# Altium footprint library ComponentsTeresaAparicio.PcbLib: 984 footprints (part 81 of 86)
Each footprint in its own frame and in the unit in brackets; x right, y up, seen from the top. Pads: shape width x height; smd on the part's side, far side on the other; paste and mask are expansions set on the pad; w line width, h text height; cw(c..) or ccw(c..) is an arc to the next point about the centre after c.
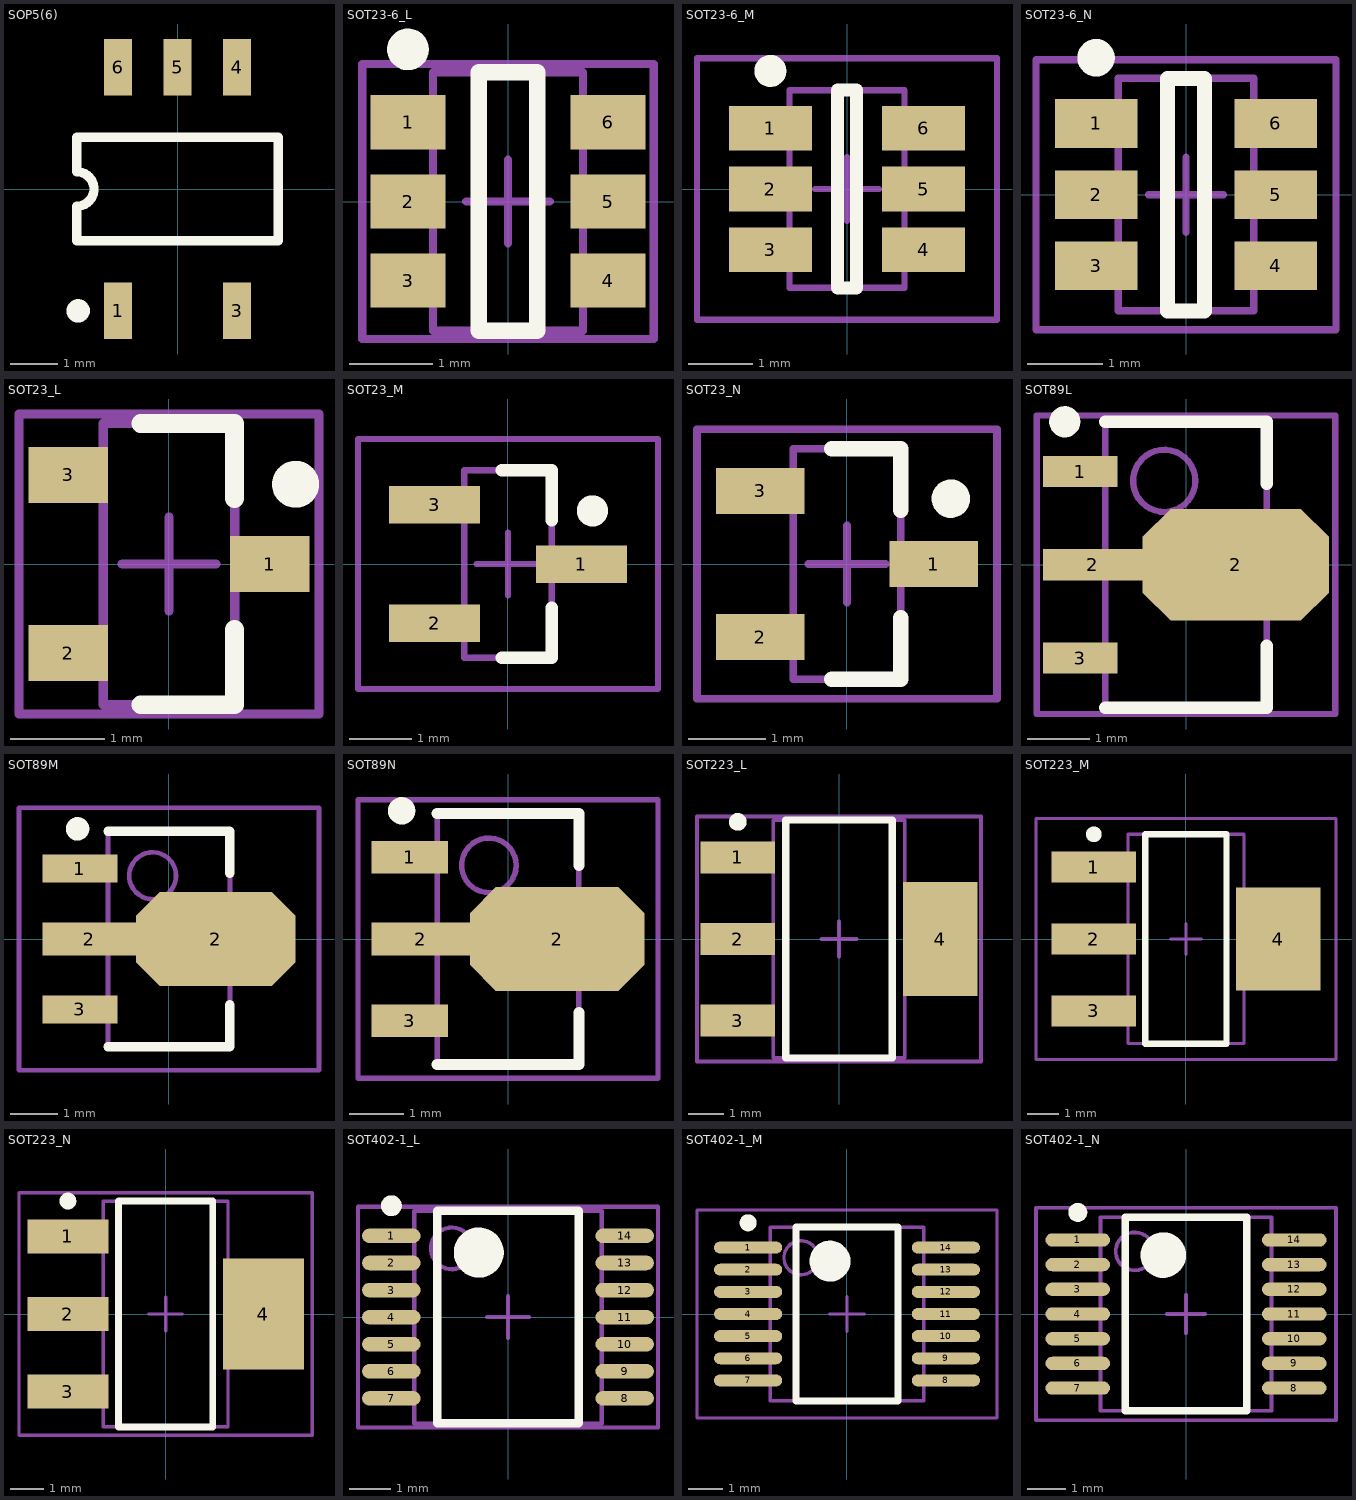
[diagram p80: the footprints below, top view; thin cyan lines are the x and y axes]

## SOP5(6) [mm] "Small Outline; 6 Leads (1 Absent); Body Width 4.4 mm; Pitch 1.27 mm"
height 2.4
pads (5):
  rect 0.6x1.2 smd: 1(-1.27,-2.6) 3(1.27,-2.6) 4(1.27,2.6) 5(0,2.6) 6(-1.27,2.6)
Top Overlay:
  circle w0.25: c-2.12,-2.6 r0.125
  lines w0.2: -2.15,-1.1 2.15,-1.1 2.15,1.1 -2.15,1.1 -2.15,0.367 cw(c-2.15,0) -2.15,-0.367 -2.15,-1.1

## SOT23-6_L [mm] "SOT23, 6-Leads, Body 2.9x1.6mm, Pitch 0.95mm, Lead Span 2.7mm, IPC High Density"
height 1.45
pads (6):
  rect 0.9x0.65 smd: 1(-1.2,0.95) 2(-1.2,0) 3(-1.2,-0.95) 4(1.2,-0.95) 5(1.2,0) 6(1.2,0.95)
Top Overlay:
  circle w0.25: c-1.2,1.825 r0.125
  lines w0.2: -0.35,-1.55 0.35,-1.55 0.35,1.55 -0.35,1.55 -0.35,-1.55
Mechanical 13:
  lines w0.1: -0.9,-1.55 -0.9,1.55 0.9,1.55 0.9,-1.55 -0.9,-1.55
Mechanical 15:
  lines w0.1: -0.5,0 0.5,0 ; 0,-0.5 0,0.5 ; -1.75,-1.65 -1.75,1.65 1.75,1.65 1.75,-1.65 -1.75,-1.65
3D body: height 1.45, standoff 0, extent -0.9,-1.55 0.9,1.55

## SOT23-6_M [mm] "SOT23, 6-Leads, Body 2.9x1.6mm, Pitch 0.95mm, Lead Span 2.7mm, IPC Low Density"
height 1.45
pads (6):
  rect 1.3x0.7 smd: 1(-1.2,0.95) 2(-1.2,0) 3(-1.2,-0.95) 4(1.2,-0.95) 5(1.2,0) 6(1.2,0.95)
Top Overlay:
  circle w0.25: c-1.2,1.85 r0.125
  lines w0.2: -0.15,-1.55 0.15,-1.55 0.15,1.55 -0.15,1.55 -0.15,-1.55
Mechanical 13:
  lines w0.1: -0.9,-1.55 -0.9,1.55 0.9,1.55 0.9,-1.55 -0.9,-1.55
Mechanical 15:
  lines w0.1: -0.5,0 0.5,0 ; 0,-0.5 0,0.5 ; -2.35,-2.05 -2.35,2.05 2.35,2.05 2.35,-2.05 -2.35,-2.05
3D body: height 1.45, standoff 0, extent -0.9,-1.55 0.9,1.55

## SOT23-6_N [mm] "SOT23, 6-Leads, Body 2.9x1.6mm, Pitch 0.95mm, Lead Span 2.7mm, IPC Medium Density"
height 1.45
pads (6):
  rect 1.1x0.65 smd: 1(-1.2,0.95) 2(-1.2,0) 3(-1.2,-0.95) 4(1.2,-0.95) 5(1.2,0) 6(1.2,0.95)
Top Overlay:
  circle w0.25: c-1.2,1.825 r0.125
  lines w0.2: -0.25,-1.55 0.25,-1.55 0.25,1.55 -0.25,1.55 -0.25,-1.55
Mechanical 13:
  lines w0.1: -0.9,-1.55 -0.9,1.55 0.9,1.55 0.9,-1.55 -0.9,-1.55
Mechanical 15:
  lines w0.1: -0.5,0 0.5,0 ; 0,-0.5 0,0.5 ; -2,-1.8 -2,1.8 2,1.8 2,-1.8 -2,-1.8
3D body: height 1.45, standoff 0, extent -0.9,-1.55 0.9,1.55

## SOT23_L [mm] "SOT23, 3-Leads, Body 2.9x1.3mm, Pitch 0.95mm, Lead Span 2.3mm - Reverse Pinning, IPC High Density"
height 1.1
pads (3):
  rect 0.85x0.6 smd: 1(1.075,0) 2(-1.075,-0.95) 3(-1.075,0.95)
Top Overlay:
  circle w0.25: c1.35,0.85 r0.125
  lines w0.2: -0.3,-1.5 0.7,-1.5 0.7,-0.7 ; -0.3,1.5 0.7,1.5 0.7,0.7
Mechanical 13:
  lines w0.1: -0.7,-1.5 0.7,-1.5 0.7,1.5 -0.7,1.5 -0.7,-1.5
Mechanical 15:
  lines w0.1: -0.5,0 0.5,0 ; 0,-0.5 0,0.5 ; -1.6,-1.6 1.6,-1.6 1.6,1.6 -1.6,1.6 -1.6,-1.6
3D body: height 1.1, standoff 0, extent -0.7,-1.5 0.7,1.5

## SOT23_M [mm] "SOT23, 3-Leads, Body 2.9x1.3mm, Pitch 0.95mm, Lead Span 2.3mm - Reverse Pinning, IPC Low Density"
height 1.1
pads (3):
  rect 1.45x0.6 smd: 1(1.175,0) 2(-1.175,-0.95) 3(-1.175,0.95)
Top Overlay:
  circle w0.25: c1.35,0.85 r0.125
  lines w0.2: -0.1,-1.5 0.7,-1.5 0.7,-0.7 ; -0.1,1.5 0.7,1.5 0.7,0.7
Mechanical 13:
  lines w0.1: -0.7,-1.5 0.7,-1.5 0.7,1.5 -0.7,1.5 -0.7,-1.5
Mechanical 15:
  lines w0.1: -0.5,0 0.5,0 ; 0,-0.5 0,0.5 ; -2.4,-2 2.4,-2 2.4,2 -2.4,2 -2.4,-2
3D body: height 1.1, standoff 0, extent -0.7,-1.5 0.7,1.5

## SOT23_N [mm] "SOT23, 3-Leads, Body 2.9x1.3mm, Pitch 0.95mm, Lead Span 2.3mm - Reverse Pinning, IPC Medium Density"
height 1.1
pads (3):
  rect 1.15x0.6 smd: 1(1.125,0) 2(-1.125,-0.95) 3(-1.125,0.95)
Top Overlay:
  circle w0.25: c1.35,0.85 r0.125
  lines w0.2: -0.2,-1.5 0.7,-1.5 0.7,-0.7 ; -0.2,1.5 0.7,1.5 0.7,0.7
Mechanical 13:
  lines w0.1: -0.7,-1.5 0.7,-1.5 0.7,1.5 -0.7,1.5 -0.7,-1.5
Mechanical 15:
  lines w0.1: -0.5,0 0.5,0 ; 0,-0.5 0,0.5 ; -1.95,-1.75 1.95,-1.75 1.95,1.75 -1.95,1.75 -1.95,-1.75
3D body: height 1.1, standoff 0, extent -0.7,-1.5 0.7,1.5

## SOT89L [mm] "SOT89, 3-Leads, Body 4.5x2.4 mm, Pitch 1.5mm, Lead Span 4.1mm, IPC High Density"
height 1.6
pads (4):
  rect 1.2x0.5 smd: 1(-1.7,1.5) 3(-1.7,-1.5)
  rect 1.6x0.5 smd: 2(-1.5,0)
  oct 3x1.8 smd: 2(0.8,0)
Top Overlay:
  circle w0.25: c-1.95,2.3 r0.125
  lines w0.2: -1.3,-2.3 1.3,-2.3 1.3,-1.3 ; -1.3,2.3 1.3,2.3 1.3,1.3
Mechanical 13:
  circle w0.1: c-0.35,1.35 r0.5
  lines w0.1: -1.3,-2.3 1.3,-2.3 1.3,2.3 -1.3,2.3 -1.3,-2.3
Mechanical 15:
  lines w0.1: -0.5,0 0.5,0 ; 0,-0.5 0,0.5 ; -2.4,-2.4 2.4,-2.4 2.4,2.4 -2.4,2.4 -2.4,-2.4
3D body: height 1.6, standoff 0, extent -1.3,-2.3 1.3,2.3

## SOT89M [mm] "SOT89, 3-Leads, Body 4.5x2.4 mm, Pitch 1.5mm, Lead Span 4.1mm, IPC Low Density"
height 1.6
pads (4):
  rect 1.6x0.6 smd: 1(-1.9,1.5) 3(-1.9,-1.5)
  rect 2x0.7 smd: 2(-1.7,0)
  oct 3.4x2 smd: 2(1,0)
Top Overlay:
  circle w0.25: c-1.95,2.35 r0.125
  lines w0.2: -1.3,-2.3 1.3,-2.3 1.3,-1.4 ; -1.3,2.3 1.3,2.3 1.3,1.4
Mechanical 13:
  circle w0.1: c-0.35,1.35 r0.5
  lines w0.1: -1.3,-2.3 1.3,-2.3 1.3,2.3 -1.3,2.3 -1.3,-2.3
Mechanical 15:
  lines w0.1: -0.5,0 0.5,0 ; 0,-0.5 0,0.5 ; -3.2,-2.8 3.2,-2.8 3.2,2.8 -3.2,2.8 -3.2,-2.8
3D body: height 1.6, standoff 0, extent -1.3,-2.3 1.3,2.3

## SOT89N [mm] "SOT89, 3-Leads, Body 4.5x2.4 mm, Pitch 1.5mm, Lead Span 4.1mm, IPC Medium Density"
height 1.6
pads (4):
  rect 1.4x0.6 smd: 1(-1.8,1.5) 3(-1.8,-1.5)
  rect 1.8x0.6 smd: 2(-1.6,0)
  oct 3.2x1.9 smd: 2(0.9,0)
Top Overlay:
  circle w0.25: c-1.95,2.35 r0.125
  lines w0.2: -1.3,-2.3 1.3,-2.3 1.3,-1.35 ; -1.3,2.3 1.3,2.3 1.3,1.35
Mechanical 13:
  circle w0.1: c-0.35,1.35 r0.5
  lines w0.1: -1.3,-2.3 -1.3,2.3 1.3,2.3 1.3,-2.3 -1.3,-2.3
Mechanical 15:
  lines w0.1: -0.5,0 0.5,0 ; 0,-0.5 0,0.5 ; -2.75,-2.55 -2.75,2.55 2.75,2.55 2.75,-2.55 -2.75,-2.55
3D body: height 1.6, standoff 0, extent -1.3,-2.3 1.3,2.3

## SOT223_L [mm] "SOT223, 4-Leads, Body 6.5x3.5mm, Pitch 2.3mm, Lead Span 7mm, IPC High Density"
height 1.7
pads (4):
  rect 2.1x0.9 smd: 1(-2.85,2.3) 2(-2.85,0) 3(-2.85,-2.3)
  rect 2.1x3.2 smd: 4(2.85,0)
Top Overlay:
  circle w0.25: c-2.85,3.3 r0.125
  lines w0.2: -1.5,-3.35 1.5,-3.35 1.5,3.35 -1.5,3.35 -1.5,-3.35
Mechanical 13:
  lines w0.1: -1.85,-3.35 1.85,-3.35 1.85,3.35 -1.85,3.35 -1.85,-3.35
Mechanical 15:
  lines w0.1: -0.5,0 0.5,0 ; 0,-0.5 0,0.5 ; -4,-3.45 4,-3.45 4,3.45 -4,3.45 -4,-3.45
3D body: height 1.7, standoff 0, extent -1.85,-3.35 1.85,3.35

## SOT223_M [mm] "SOT223, 4-Leads, Body 6.5x3.5mm, Pitch 2.3mm, Lead Span 7mm, IPC Low Density"
height 1.7
pads (4):
  rect 2.7x1 smd: 1(-2.95,2.3) 2(-2.95,0) 3(-2.95,-2.3)
  rect 2.7x3.3 smd: 4(2.95,0)
Top Overlay:
  circle w0.25: c-2.95,3.35 r0.125
  lines w0.2: -1.3,-3.35 -1.3,3.35 1.3,3.35 1.3,-3.35 -1.3,-3.35
Mechanical 13:
  lines w0.1: -1.85,-3.35 -1.85,3.35 1.85,3.35 1.85,-3.35 -1.85,-3.35
Mechanical 15:
  lines w0.1: -0.5,0 0.5,0 ; 0,-0.5 0,0.5 ; -4.8,-3.85 -4.8,3.85 4.8,3.85 4.8,-3.85 -4.8,-3.85
3D body: height 1.7, standoff 0, extent -1.85,-3.35 1.85,3.35

## SOT223_N [mm] "SOT223, 4-Leads, Body 6.5x3.5mm, Pitch 2.3mm, Lead Span 7mm, IPC Medium Density"
height 1.7
pads (4):
  rect 2.4x1 smd: 1(-2.9,2.3) 2(-2.9,0) 3(-2.9,-2.3)
  rect 2.4x3.3 smd: 4(2.9,0)
Top Overlay:
  circle w0.25: c-2.9,3.35 r0.125
  lines w0.2: -1.4,-3.35 -1.4,3.35 1.4,3.35 1.4,-3.35 -1.4,-3.35
Mechanical 13:
  lines w0.1: -1.85,-3.35 -1.85,3.35 1.85,3.35 1.85,-3.35 -1.85,-3.35
Mechanical 15:
  lines w0.1: -0.5,0 0.5,0 ; 0,-0.5 0,0.5 ; -4.35,-3.6 -4.35,3.6 4.35,3.6 4.35,-3.6 -4.35,-3.6
3D body: height 1.7, standoff 0, extent -1.85,-3.35 1.85,3.35

## SOT402-1_L [mm] "TSOP, 14-Leads, Body 5x4.4mm, Pitch 0.65mm, IPC High Density"
height 1.1
pads (14):
  oval 1.4x0.35 smd: 1(-2.8,1.95) 2(-2.8,1.3) 3(-2.8,0.65) 4(-2.8,0) 5(-2.8,-0.65) 6(-2.8,-1.3) 7(-2.8,-1.95) 8(2.8,-1.95) 9(2.8,-1.3) 10(2.8,-0.65) 11(2.8,0) 12(2.8,0.65) 13(2.8,1.3) 14(2.8,1.95)
Top Overlay:
  circle w0.25: c-2.8,2.675 r0.125
  circle w0.6: c-0.7,1.55 r0.3
  lines w0.2: -1.7,-2.55 -1.7,2.55 1.7,2.55 1.7,-2.55 -1.7,-2.55
Mechanical 13:
  circle w0.1: c-1.35,1.65 r0.5
  lines w0.1: -2.25,-2.55 -2.25,2.55 2.25,2.55 2.25,-2.55 -2.25,-2.55
Mechanical 15:
  lines w0.1: -0.5,0 0.5,0 ; 0,-0.5 0,0.5 ; -3.6,-2.65 -3.6,2.65 3.6,2.65 3.6,-2.65 -3.6,-2.65
3D body: height 1.1, standoff 0, extent -2.25,-2.55 2.25,2.55

## SOT402-1_M [mm] "TSOP, 14-Leads, Body 5x4.4mm, Pitch 0.65mm, IPC Low Density"
height 1.1
pads (14):
  oval 2x0.35 smd: 1(-2.9,1.95) 2(-2.9,1.3) 3(-2.9,0.65) 4(-2.9,0) 5(-2.9,-0.65) 6(-2.9,-1.3) 7(-2.9,-1.95) 8(2.9,-1.95) 9(2.9,-1.3) 10(2.9,-0.65) 11(2.9,0) 12(2.9,0.65) 13(2.9,1.3) 14(2.9,1.95)
Top Overlay:
  circle w0.25: c-2.9,2.675 r0.125
  circle w0.6: c-0.5,1.55 r0.3
  lines w0.2: -1.5,-2.55 -1.5,2.55 1.5,2.55 1.5,-2.55 -1.5,-2.55
Mechanical 13:
  circle w0.1: c-1.35,1.65 r0.5
  lines w0.1: -2.25,-2.55 -2.25,2.55 2.25,2.55 2.25,-2.55 -2.25,-2.55
Mechanical 15:
  lines w0.1: -0.5,0 0.5,0 ; 0,-0.5 0,0.5 ; -4.4,-3.05 -4.4,3.05 4.4,3.05 4.4,-3.05 -4.4,-3.05
3D body: height 1.1, standoff 0, extent -2.25,-2.55 2.25,2.55

## SOT402-1_N [mm] "TSOP, 14-Leads, Body 5x4.4mm, Pitch 0.65mm, IPC Medium Density"
height 1.1
pads (14):
  oval 1.7x0.35 smd: 1(-2.85,1.95) 2(-2.85,1.3) 3(-2.85,0.65) 4(-2.85,0) 5(-2.85,-0.65) 6(-2.85,-1.3) 7(-2.85,-1.95) 8(2.85,-1.95) 9(2.85,-1.3) 10(2.85,-0.65) 11(2.85,0) 12(2.85,0.65) 13(2.85,1.3) 14(2.85,1.95)
Top Overlay:
  circle w0.25: c-2.85,2.675 r0.125
  circle w0.6: c-0.6,1.55 r0.3
  lines w0.2: -1.6,-2.55 -1.6,2.55 1.6,2.55 1.6,-2.55 -1.6,-2.55
Mechanical 13:
  circle w0.1: c-1.35,1.65 r0.5
  lines w0.1: -2.25,-2.55 -2.25,2.55 2.25,2.55 2.25,-2.55 -2.25,-2.55
Mechanical 15:
  lines w0.1: -0.5,0 0.5,0 ; 0,-0.5 0,0.5 ; -3.95,-2.8 -3.95,2.8 3.95,2.8 3.95,-2.8 -3.95,-2.8
3D body: height 1.1, standoff 0, extent -2.25,-2.55 2.25,2.55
